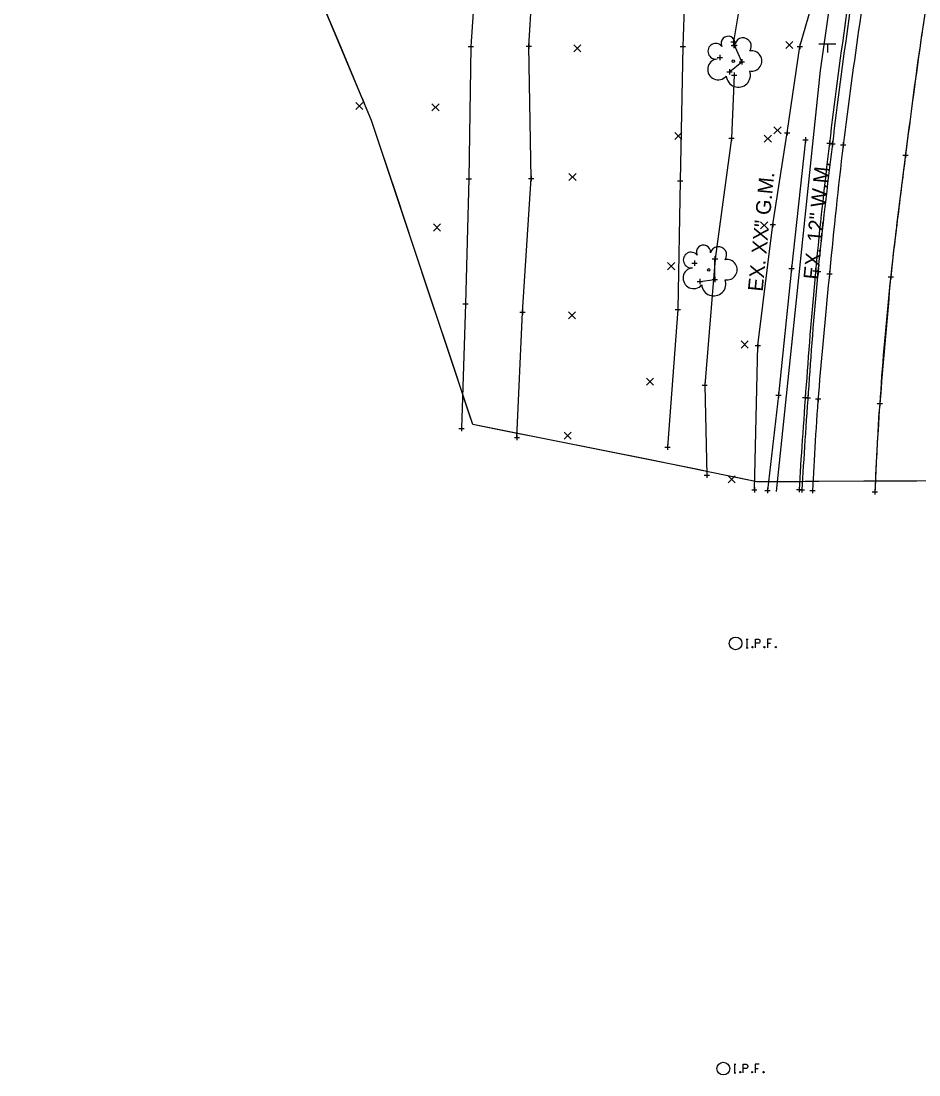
# Model space of a CAD drawing. Extents: x 1324089 to 1329959, y 459099 to 462017.
# Drawn here: x 1324541.1 to 1324710.1, y 459109.6 to 459307.9 of the extents above; entities that cross this region are included whole.
import ezdxf

# ---------------------------------------------------------------- set-up
doc = ezdxf.new("R2010")
doc.units = 0
for name, color, linetype in [('PM_X_Lane_Line', 7, 'Continuous'), ('PM_X_Surveyed_Line', 7, 'Continuous'), ('PV_X_Curb', 7, 'Continuous'), ('PV_X_EOP', 7, 'Continuous'), ('SC_Scratch1', 7, 'Continuous'), ('SN_X_Public', 7, 'Continuous'), ('SV_X_Break_Lines', 7, 'Continuous'), ('SV_X_Mon_Cells_Found', 7, 'Continuous'), ('SV_X_Random_Point', 7, 'Continuous'), ('SV_X_Shot_Marker', 7, 'Continuous'), ('UT_X_Gas', 7, 'Continuous'), ('UT_X_Gas_Text', 7, 'Continuous'), ('UT_X_Water', 7, 'Continuous'), ('UT_X_Water_Text', 7, 'Continuous'), ('VG_X_Cells', 7, 'Continuous'), ('VG_X_Flower_Bed', 7, 'Continuous')]:
    doc.layers.add(name, color=color, linetype=linetype)

msp = doc.modelspace()

# ---------------------------------------------------------------- linework, layer by layer
at = {"layer": 'PM_X_Lane_Line'}
for centre, radius, start, end in [((1325357.86, 459210.87), 654.07, 171.51048, 172.24546), ((1327258.01, 458952.12), 2571.76, 172.24546, 172.61612), ((1326359.8, 459068.52), 1666.03, 172.61612, 173.06999), ((1325632.45, 459156.92), 933.33, 173.06999, 173.6764), ((1339856.26, 457945.01), 15208.41, 175.046029, 175.130785), ((1324762.68, 459253.31), 58.24, 173.6764, 175.046), ((1324869.87, 459221.69), 167.75, 175.1308, 176.845), ((1325603.46, 459181.25), 902.44, 176.84495, 177.58397)]:
    msp.add_arc(centre, radius, start, end, dxfattribs=at)
at = {"layer": 'PM_X_Surveyed_Line'}
msp.add_open_spline([(1324720.83, 459365.01), (1324717.36, 459354.42), (1324715.9, 459334.74), (1324710.69, 459307.46), (1324707.68, 459283.27), (1324704.59, 459259.48), (1324702.8, 459238.34), (1324702.05, 459224.84), (1324701.82, 459219.29)], degree=3, dxfattribs=at)
at = {"layer": 'PV_X_Curb'}
for points in [[(1324554.41, 459525.77), (1324560.16, 459519.51), (1324574.45, 459509.18), (1324595.04, 459493.36), (1324617.9, 459478.11), (1324641.77, 459463.54), (1324665.2, 459452.03), (1324684.98, 459441.52), (1324698.95, 459427.62), (1324704.89, 459409.37), (1324705.69, 459390.23), (1324705.74, 459370.4), (1324703.35, 459350.36), (1324699.71, 459329.94), (1324696.22, 459308.21), (1324693.2, 459284.97), (1324690.54, 459260.98), (1324688.84, 459239.23), (1324687.9, 459225.51), (1324687.54, 459219.73)], [(1324554.61, 459526.26), (1324562.73, 459523.45), (1324573.61, 459508), (1324595.63, 459494.27), (1324618.06, 459478.41), (1324642.02, 459464.01), (1324665.5, 459452.57), (1324685.24, 459441.87), (1324699.44, 459427.92), (1324705.38, 459409.51), (1324706.27, 459390.25), (1324706.24, 459370.35), (1324703.79, 459350.24), (1324700.16, 459329.85), (1324696.79, 459308.11), (1324693.79, 459284.88), (1324690.96, 459260.88), (1324689.32, 459239.14), (1324688.41, 459225.43), (1324688.07, 459219.66)]]:
    msp.add_open_spline(points, degree=3, dxfattribs=at)
at = {"layer": 'PV_X_EOP'}
msp.add_open_spline([(1324556.16, 459527.57), (1324561.48, 459521.01), (1324576.43, 459511.53), (1324596.29, 459495.04), (1324619.32, 459480.24), (1324643.04, 459465.7), (1324666.45, 459454.07), (1324686.66, 459443.46), (1324700.99, 459428.91), (1324707.44, 459410.05), (1324708.19, 459390.35), (1324708.25, 459370.27), (1324705.92, 459350.01), (1324702.09, 459329.59), (1324698.99, 459307.8), (1324695.7, 459284.61), (1324693.29, 459260.58), (1324691.16, 459238.91), (1324690.35, 459225.3), (1324690.06, 459219.55)], degree=3, dxfattribs=at)
at = {"layer": 'SC_Scratch1'}
for p, q in [((1324607.09, 459289.13), (1324595.37, 459317.04)), ((1324626.14, 459231.96), (1324607.09, 459289.13)), ((1324663.15, 459224.6), (1324626.14, 459231.96)), ((1324679.58, 459221.18), (1324663.15, 459224.6)), ((1324759.65, 459221.61), (1324679.58, 459221.18))]:
    msp.add_line(p, q, dxfattribs=at)
msp.add_lwpolyline([(1324719.74, 459221.39), (1324709.74, 459221.34), (1324699.74, 459221.29), (1324690.15, 459221.23), (1324689.74, 459221.23), (1324688.71, 459221.23), (1324688.17, 459221.22), (1324687.77, 459221.22), (1324687.64, 459221.22), (1324683.31, 459221.2), (1324681.76, 459221.19), (1324679.74, 459221.18), (1324679.58, 459221.18), (1324675.12, 459222.1), (1324674.74, 459222.19), (1324670.14, 459223.14), (1324669.95, 459223.18), (1324668.8, 459223.42), (1324663.15, 459224.6), (1324661.31, 459224.97), (1324660.15, 459225.2), (1324650.34, 459227.15), (1324640.54, 459229.1), (1324637.75, 459229.65), (1324634.49, 459230.3), (1324630.73, 459231.05), (1324626.14, 459231.96), (1324625.46, 459234.01), (1324624.46, 459237.01), (1324624.2, 459237.78), (1324622.6, 459242.59), (1324621.3, 459246.5), (1324618.13, 459255.99), (1324614.97, 459265.47), (1324611.81, 459274.96), (1324608.65, 459284.45), (1324607.72, 459287.26), (1324607.09, 459289.13), (1324605.95, 459291.86), (1324605.48, 459292.96), (1324605.13, 459293.8), (1324601.26, 459303.02), (1324597.38, 459312.24)], dxfattribs=at)
at = {"layer": 'SN_X_Public'}
for p, q in [((1324691.3, 459303.58), (1324694.5, 459303.58)), ((1324692.9, 459303.58), (1324692.9, 459301.98)), ((1324692.9, 459303.58), (1324692.9, 459303.58))]:
    msp.add_line(p, q, dxfattribs=at)
at = {"layer": 'SV_X_Break_Lines'}
for p, q in [((1324627.42, 459327.25), (1324625.76, 459303.05)), ((1324636.69, 459303.12), (1324638.1, 459325.97)), ((1324666.42, 459327.01), (1324665.66, 459303.05)), ((1324625.76, 459303.05), (1324625.38, 459278.18)), ((1324637.13, 459278.25), (1324636.69, 459303.12)), ((1324665.66, 459303.05), (1324665.14, 459277.83)), ((1324688.75, 459285.51), (1324686.14, 459261.32)), ((1324625.38, 459278.18), (1324624.77, 459254.65)), ((1324635.49, 459253.09), (1324637.13, 459278.25)), ((1324665.14, 459277.83), (1324664.73, 459253.6)), ((1324686.14, 459261.32), (1324683.65, 459237.51)), ((1324671.69, 459259.25), (1324671.69, 459259.25)), ((1324624.77, 459254.65), (1324623.98, 459231.21)), ((1324634.45, 459229.53), (1324635.49, 459253.09)), ((1324664.73, 459253.6), (1324662.78, 459227.71)), ((1324683.65, 459237.51), (1324681.58, 459219.58))]:
    msp.add_line(p, q, dxfattribs=at)
for points in [[(1324541.09, 459511.12), (1324561.98, 459492.74), (1324584.53, 459475.42), (1324605.25, 459461.38), (1324621.29, 459450.83), (1324632.11, 459444.1), (1324650.07, 459430.27), (1324666.2, 459410.06), (1324661.44, 459407.26), (1324665.74, 459392.42), (1324674.5, 459384.98), (1324677.71, 459376.69), (1324678.67, 459361.24), (1324681.49, 459352.29), (1324680.91, 459341.63), (1324680.37, 459334.21), (1324672.68, 459329.65), (1324675.04, 459320.04), (1324676.26, 459310.34), (1324675.18, 459303.96)], [(1324675.32, 459297.68), (1324674.85, 459285.81), (1324671.78, 459263.15), (1324669.78, 459239.4), (1324670.16, 459222.45)]]:
    msp.add_lwpolyline(points, dxfattribs=at)
at = {"layer": 'SV_X_Mon_Cells_Found'}
for points in [[(1324677.62, 459191.59), (1324677.97, 459191.59)], [(1324677.79, 459189.99), (1324677.79, 459191.59)], [(1324679.36, 459189.99), (1324679.36, 459191.59), (1324679.89, 459191.59), (1324679.94, 459191.58), (1324680.02, 459191.55), (1324680.05, 459191.53), (1324680.09, 459191.5), (1324680.13, 459191.44), (1324680.16, 459191.38), (1324680.18, 459191.28), (1324680.18, 459191.12), (1324680.17, 459191.07), (1324680.15, 459191), (1324680.11, 459190.91), (1324680.06, 459190.87), (1324680.03, 459190.85), (1324679.98, 459190.82), (1324679.89, 459190.81), (1324679.36, 459190.81)], [(1324682.37, 459191.59), (1324681.61, 459191.59), (1324681.61, 459189.99)], [(1324681.61, 459190.81), (1324682.15, 459190.81)], [(1324677.62, 459189.99), (1324677.97, 459189.99)], [(1324678.75, 459190.21), (1324678.81, 459190.21), (1324678.84, 459190.18), (1324678.87, 459190.13), (1324678.87, 459190.07), (1324678.84, 459190.02), (1324678.81, 459189.99), (1324678.75, 459189.99), (1324678.72, 459190.02), (1324678.69, 459190.07), (1324678.69, 459190.13), (1324678.72, 459190.18), (1324678.75, 459190.21)], [(1324681, 459190.21), (1324681.06, 459190.21), (1324681.09, 459190.18), (1324681.12, 459190.13), (1324681.12, 459190.07), (1324681.09, 459190.02), (1324681.06, 459189.99), (1324681, 459189.99), (1324680.97, 459190.02), (1324680.93, 459190.07), (1324680.93, 459190.13), (1324680.97, 459190.18), (1324681, 459190.21)], [(1324683.15, 459190.21), (1324683.2, 459190.21), (1324683.24, 459190.18), (1324683.27, 459190.13), (1324683.27, 459190.07), (1324683.24, 459190.02), (1324683.2, 459189.99), (1324683.15, 459189.99), (1324683.12, 459190.02), (1324683.08, 459190.07), (1324683.08, 459190.13), (1324683.12, 459190.18), (1324683.15, 459190.21)], [(1324675.31, 459111.62), (1324675.66, 459111.62)], [(1324675.48, 459110.02), (1324675.48, 459111.62)], [(1324677.05, 459110.02), (1324677.05, 459111.62), (1324677.58, 459111.62), (1324677.63, 459111.61), (1324677.71, 459111.58), (1324677.74, 459111.56), (1324677.78, 459111.53), (1324677.82, 459111.47), (1324677.85, 459111.41), (1324677.88, 459111.31), (1324677.88, 459111.15), (1324677.86, 459111.1), (1324677.84, 459111.03), (1324677.8, 459110.94), (1324677.75, 459110.9), (1324677.72, 459110.88), (1324677.67, 459110.85), (1324677.58, 459110.84), (1324677.05, 459110.84)], [(1324680.06, 459111.62), (1324679.3, 459111.62), (1324679.3, 459110.02)], [(1324675.31, 459110.02), (1324675.66, 459110.02)], [(1324676.44, 459110.24), (1324676.5, 459110.24), (1324676.53, 459110.21), (1324676.56, 459110.16), (1324676.56, 459110.1), (1324676.53, 459110.05), (1324676.5, 459110.02), (1324676.44, 459110.02), (1324676.41, 459110.05), (1324676.38, 459110.1), (1324676.38, 459110.16), (1324676.41, 459110.21), (1324676.44, 459110.24)], [(1324678.69, 459110.24), (1324678.75, 459110.24), (1324678.78, 459110.21), (1324678.81, 459110.16), (1324678.81, 459110.1), (1324678.78, 459110.05), (1324678.75, 459110.02), (1324678.69, 459110.02), (1324678.66, 459110.05), (1324678.63, 459110.1), (1324678.63, 459110.16), (1324678.66, 459110.21), (1324678.69, 459110.24)], [(1324679.3, 459110.84), (1324679.84, 459110.84)], [(1324680.84, 459110.24), (1324680.9, 459110.24), (1324680.93, 459110.21), (1324680.96, 459110.16), (1324680.96, 459110.1), (1324680.93, 459110.05), (1324680.9, 459110.02), (1324680.84, 459110.02), (1324680.81, 459110.05), (1324680.77, 459110.1), (1324680.77, 459110.16), (1324680.81, 459110.21), (1324680.84, 459110.24)]]:
    msp.add_lwpolyline(points, dxfattribs=at)
for centre in [(1324675.6, 459190.79), (1324673.29, 459110.82)]:
    msp.add_circle(centre, 1.2, dxfattribs=at)
at = {"layer": 'SV_X_Random_Point'}
for p, q in [((1324685.07, 459302.68), (1324686.4, 459304.02)), ((1324685.07, 459304.02), (1324686.4, 459302.68)), ((1324645.16, 459302.08), (1324646.49, 459303.42)), ((1324645.16, 459303.42), (1324646.49, 459302.08)), ((1324604.09, 459291.22), (1324605.42, 459292.55)), ((1324604.09, 459292.55), (1324605.42, 459291.22)), ((1324618.44, 459290.95), (1324619.77, 459292.28)), ((1324618.44, 459292.28), (1324619.77, 459290.95)), ((1324682.83, 459286.63), (1324684.16, 459287.97)), ((1324682.83, 459287.97), (1324684.16, 459286.63)), ((1324664.14, 459285.56), (1324665.47, 459286.9)), ((1324664.14, 459286.9), (1324665.47, 459285.56)), ((1324681, 459285.09), (1324682.34, 459286.43)), ((1324681, 459286.43), (1324682.34, 459285.09)), ((1324644.23, 459277.86), (1324645.57, 459279.19)), ((1324644.23, 459279.19), (1324645.57, 459277.86)), ((1324680.32, 459268.77), (1324681.65, 459270.1)), ((1324680.32, 459270.1), (1324681.65, 459268.77)), ((1324618.72, 459268.37), (1324620.06, 459269.7)), ((1324618.72, 459269.7), (1324620.06, 459268.37)), ((1324662.8, 459261.09), (1324664.14, 459262.43)), ((1324662.8, 459262.43), (1324664.14, 459261.09)), ((1324644.14, 459251.82), (1324645.47, 459253.16)), ((1324644.14, 459253.16), (1324645.47, 459251.82)), ((1324676.64, 459246.36), (1324677.97, 459247.69)), ((1324676.64, 459247.69), (1324677.97, 459246.36)), ((1324658.8, 459239.36), (1324660.13, 459240.69)), ((1324658.8, 459240.69), (1324660.13, 459239.36)), ((1324643.31, 459229.22), (1324644.64, 459230.56)), ((1324643.31, 459230.56), (1324644.64, 459229.22)), ((1324674.22, 459221.01), (1324675.55, 459222.34)), ((1324674.22, 459222.34), (1324675.55, 459221.01))]:
    msp.add_line(p, q, dxfattribs=at)
at = {"layer": 'SV_X_Shot_Marker'}
for p, q in [((1324625.76, 459303.55), (1324625.76, 459302.55)), ((1324636.69, 459303.62), (1324636.69, 459302.62)), ((1324665.66, 459303.55), (1324665.66, 459302.55)), ((1324674.68, 459303.96), (1324675.68, 459303.96)), ((1324675.18, 459304.46), (1324675.18, 459303.46)), ((1324675.18, 459303.96), (1324675.18, 459303.96)), ((1324675.29, 459303.77), (1324675.29, 459302.77)), ((1324675.38, 459303.83), (1324675.38, 459302.83)), ((1324687.69, 459303.61), (1324687.69, 459302.61)), ((1324625.26, 459303.05), (1324626.26, 459303.05)), ((1324625.76, 459303.05), (1324625.76, 459303.05)), ((1324636.19, 459303.12), (1324637.19, 459303.12)), ((1324636.69, 459303.12), (1324636.69, 459303.12)), ((1324665.16, 459303.05), (1324666.16, 459303.05)), ((1324665.66, 459303.05), (1324665.66, 459303.05)), ((1324674.79, 459303.27), (1324675.79, 459303.27)), ((1324674.88, 459303.33), (1324675.88, 459303.33)), ((1324675.29, 459303.27), (1324675.29, 459303.27)), ((1324675.38, 459303.33), (1324675.38, 459303.33)), ((1324687.19, 459303.11), (1324688.19, 459303.11)), ((1324687.69, 459303.11), (1324687.69, 459303.11)), ((1324672.14, 459301), (1324673.14, 459301)), ((1324672.64, 459301.5), (1324672.64, 459300.5)), ((1324672.64, 459301), (1324672.64, 459301)), ((1324676.3, 459300.2), (1324677.3, 459300.2)), ((1324676.3, 459300.2), (1324677.3, 459300.2)), ((1324676.8, 459300.7), (1324676.8, 459299.7)), ((1324676.8, 459300.7), (1324676.8, 459299.7)), ((1324676.8, 459300.2), (1324676.8, 459300.2)), ((1324676.8, 459300.2), (1324676.8, 459300.2)), ((1324673.97, 459298.34), (1324674.97, 459298.34)), ((1324674.47, 459298.84), (1324674.47, 459297.84)), ((1324674.47, 459298.34), (1324674.47, 459298.34)), ((1324674.82, 459297.68), (1324675.82, 459297.68)), ((1324675.32, 459298.18), (1324675.32, 459297.18)), ((1324675.32, 459297.68), (1324675.32, 459297.68)), ((1324674.35, 459285.81), (1324675.35, 459285.81)), ((1324674.85, 459286.31), (1324674.85, 459285.31)), ((1324674.85, 459285.81), (1324674.85, 459285.81)), ((1324684.82, 459286.87), (1324685.82, 459286.87)), ((1324685.32, 459287.37), (1324685.32, 459286.37)), ((1324685.32, 459286.87), (1324685.32, 459286.87)), ((1324688.75, 459286.01), (1324688.75, 459285.01)), ((1324688.25, 459285.51), (1324689.25, 459285.51)), ((1324688.75, 459285.51), (1324688.75, 459285.51)), ((1324692.77, 459284.92), (1324693.77, 459284.92)), ((1324693.27, 459285.42), (1324693.27, 459284.42)), ((1324693.27, 459284.92), (1324693.27, 459284.92)), ((1324693.32, 459284.78), (1324694.32, 459284.78)), ((1324693.82, 459285.28), (1324693.82, 459284.28)), ((1324693.82, 459284.78), (1324693.82, 459284.78)), ((1324695.37, 459284.58), (1324696.37, 459284.58)), ((1324695.87, 459285.08), (1324695.87, 459284.08)), ((1324695.87, 459284.58), (1324695.87, 459284.58)), ((1324707.08, 459282.63), (1324708.08, 459282.63)), ((1324707.58, 459283.13), (1324707.58, 459282.13)), ((1324707.58, 459282.63), (1324707.58, 459282.63)), ((1324624.88, 459278.18), (1324625.88, 459278.18)), ((1324625.38, 459278.68), (1324625.38, 459277.68)), ((1324625.38, 459278.18), (1324625.38, 459278.18)), ((1324636.63, 459278.25), (1324637.63, 459278.25)), ((1324637.13, 459278.75), (1324637.13, 459277.75)), ((1324637.13, 459278.25), (1324637.13, 459278.25)), ((1324664.64, 459277.83), (1324665.64, 459277.83)), ((1324665.14, 459278.33), (1324665.14, 459277.33)), ((1324665.14, 459277.83), (1324665.14, 459277.83)), ((1324682.59, 459270.07), (1324682.59, 459269.07)), ((1324682.09, 459269.57), (1324683.09, 459269.57)), ((1324682.59, 459269.57), (1324682.59, 459269.57)), ((1324667.39, 459262.35), (1324668.39, 459262.35)), ((1324667.89, 459262.85), (1324667.89, 459261.85)), ((1324667.89, 459262.35), (1324667.89, 459262.35)), ((1324671.22, 459263.16), (1324672.22, 459263.16)), ((1324671.28, 459263.15), (1324672.28, 459263.15)), ((1324671.28, 459263.15), (1324672.28, 459263.15)), ((1324671.72, 459263.66), (1324671.72, 459262.66)), ((1324671.72, 459263.16), (1324671.72, 459263.16)), ((1324671.78, 459263.65), (1324671.78, 459262.65)), ((1324671.78, 459263.65), (1324671.78, 459262.65)), ((1324671.78, 459263.15), (1324671.78, 459263.15)), ((1324671.78, 459263.15), (1324671.78, 459263.15)), ((1324685.64, 459261.32), (1324686.64, 459261.32)), ((1324686.14, 459261.82), (1324686.14, 459260.82)), ((1324686.14, 459261.32), (1324686.14, 459261.32)), ((1324690.16, 459260.88), (1324691.16, 459260.88)), ((1324690.62, 459260.77), (1324691.62, 459260.77)), ((1324690.66, 459261.38), (1324690.66, 459260.38)), ((1324690.66, 459260.88), (1324690.66, 459260.88)), ((1324691.12, 459261.27), (1324691.12, 459260.27)), ((1324691.12, 459260.77), (1324691.12, 459260.77)), ((1324692.77, 459260.32), (1324693.77, 459260.32)), ((1324693.27, 459260.82), (1324693.27, 459259.82)), ((1324693.27, 459260.32), (1324693.27, 459260.32)), ((1324704.8, 459260.23), (1324704.8, 459259.23)), ((1324668.35, 459258.87), (1324669.35, 459258.87)), ((1324668.85, 459259.37), (1324668.85, 459258.37)), ((1324668.85, 459258.87), (1324668.85, 459258.87)), ((1324671.19, 459259.25), (1324672.19, 459259.25)), ((1324671.19, 459259.25), (1324672.19, 459259.25)), ((1324671.19, 459259.25), (1324672.19, 459259.25)), ((1324671.69, 459259.75), (1324671.69, 459258.75)), ((1324671.69, 459259.75), (1324671.69, 459258.75)), ((1324671.69, 459259.75), (1324671.69, 459258.75)), ((1324671.69, 459259.25), (1324671.69, 459259.25)), ((1324671.69, 459259.25), (1324671.69, 459259.25)), ((1324671.69, 459259.25), (1324671.69, 459259.25)), ((1324704.3, 459259.73), (1324705.3, 459259.73)), ((1324704.8, 459259.73), (1324704.8, 459259.73)), ((1324624.27, 459254.65), (1324625.27, 459254.65)), ((1324624.77, 459255.15), (1324624.77, 459254.15)), ((1324624.77, 459254.65), (1324624.77, 459254.65)), ((1324664.73, 459254.1), (1324664.73, 459253.1)), ((1324634.99, 459253.09), (1324635.99, 459253.09)), ((1324635.49, 459253.59), (1324635.49, 459252.59)), ((1324635.49, 459253.09), (1324635.49, 459253.09)), ((1324664.23, 459253.6), (1324665.23, 459253.6)), ((1324664.73, 459253.6), (1324664.73, 459253.6)), ((1324679.27, 459246.86), (1324680.27, 459246.86)), ((1324679.77, 459247.36), (1324679.77, 459246.36)), ((1324679.77, 459246.86), (1324679.77, 459246.86)), ((1324669.28, 459239.4), (1324670.28, 459239.4)), ((1324669.78, 459239.9), (1324669.78, 459238.9)), ((1324669.78, 459239.4), (1324669.78, 459239.4)), ((1324683.15, 459237.51), (1324684.15, 459237.51)), ((1324683.65, 459238.01), (1324683.65, 459237.01)), ((1324683.65, 459237.51), (1324683.65, 459237.51)), ((1324688.22, 459237.06), (1324689.22, 459237.06)), ((1324688.7, 459236.97), (1324689.7, 459236.97)), ((1324688.72, 459237.56), (1324688.72, 459236.56)), ((1324688.72, 459237.06), (1324688.72, 459237.06)), ((1324689.2, 459237.47), (1324689.2, 459236.47)), ((1324689.2, 459236.97), (1324689.2, 459236.97)), ((1324690.63, 459236.79), (1324691.63, 459236.79)), ((1324691.13, 459237.29), (1324691.13, 459236.29)), ((1324691.13, 459236.79), (1324691.13, 459236.79)), ((1324702.73, 459236.42), (1324702.73, 459235.42)), ((1324702.23, 459235.92), (1324703.23, 459235.92)), ((1324702.73, 459235.92), (1324702.73, 459235.92)), ((1324623.48, 459231.21), (1324624.48, 459231.21)), ((1324623.98, 459231.71), (1324623.98, 459230.71)), ((1324623.98, 459231.21), (1324623.98, 459231.21)), ((1324633.95, 459229.53), (1324634.95, 459229.53)), ((1324634.45, 459230.03), (1324634.45, 459229.03)), ((1324634.45, 459229.53), (1324634.45, 459229.53)), ((1324662.78, 459228.21), (1324662.78, 459227.21)), ((1324662.28, 459227.71), (1324663.28, 459227.71)), ((1324662.78, 459227.71), (1324662.78, 459227.71)), ((1324669.66, 459222.45), (1324670.66, 459222.45)), ((1324670.16, 459222.95), (1324670.16, 459221.95)), ((1324670.16, 459222.45), (1324670.16, 459222.45)), ((1324678.63, 459219.68), (1324679.63, 459219.68)), ((1324679.13, 459220.18), (1324679.13, 459219.18)), ((1324679.13, 459219.68), (1324679.13, 459219.68)), ((1324681.08, 459219.58), (1324682.08, 459219.58)), ((1324681.58, 459220.08), (1324681.58, 459219.08)), ((1324681.58, 459219.58), (1324681.58, 459219.58)), ((1324687.04, 459219.73), (1324688.04, 459219.73)), ((1324687.54, 459220.23), (1324687.54, 459219.23)), ((1324687.54, 459219.73), (1324687.54, 459219.73)), ((1324687.57, 459219.66), (1324688.57, 459219.66)), ((1324688.07, 459220.16), (1324688.07, 459219.16)), ((1324688.07, 459219.66), (1324688.07, 459219.66)), ((1324689.56, 459219.55), (1324690.56, 459219.55)), ((1324690.06, 459220.05), (1324690.06, 459219.05)), ((1324690.06, 459219.55), (1324690.06, 459219.55)), ((1324701.32, 459219.29), (1324702.32, 459219.29)), ((1324701.82, 459219.79), (1324701.82, 459218.79)), ((1324701.82, 459219.29), (1324701.82, 459219.29))]:
    msp.add_line(p, q, dxfattribs=at)
at = {"layer": 'UT_X_Gas'}
msp.add_lwpolyline([(1324679.13, 459219.68), (1324679.77, 459246.86), (1324682.59, 459269.57), (1324685.32, 459286.87), (1324687.69, 459303.11), (1324691.63, 459316.77), (1324694.22, 459329.35), (1324695.55, 459341.62), (1324697.28, 459354.27), (1324699.79, 459367.29)], dxfattribs=at)
at = {"layer": 'UT_X_Water'}
msp.add_lwpolyline([(1324683.28, 459219.36), (1324691.61, 459298.59), (1324698.63, 459347.92), (1324699.63, 459354.94), (1324721.27, 459442.34), (1324756.06, 459540.19), (1324772.19, 459580.09), (1324802.34, 459646.28), (1324825.1, 459690.99), (1324841.26, 459722.73), (1324902.17, 459810.08), (1324917.22, 459828.86)], dxfattribs=at)
at = {"layer": 'VG_X_Cells'}
for centre in [(1324675.17, 459300.32), (1324670.54, 459261.05)]:
    msp.add_circle(centre, 0.24, dxfattribs=at)
for centre, radius, start, end in [((1324671.86, 459302.18), 1.47, 39.0625, 279.5412), ((1324674.19, 459303.69), 1.32, 354.0047, 205.9741), ((1324677, 459303.15), 1.55, 323.83, 165.0376), ((1324678.63, 459300.35), 1.91, 259.1453, 101.4596), ((1324672.32, 459298.77), 1.97, 96.1722, 320.5737), ((1324676.12, 459297.71), 2.28, 184.9476, 19.4572), ((1324667.23, 459262.91), 1.47, 39.0625, 279.5412), ((1324669.56, 459264.42), 1.32, 354.0047, 205.9741), ((1324672.37, 459263.88), 1.55, 323.83, 165.0376), ((1324674, 459261.09), 1.91, 259.1453, 101.4596), ((1324667.69, 459259.5), 1.97, 96.1722, 320.5737), ((1324671.49, 459258.44), 2.28, 184.9476, 19.4572)]:
    msp.add_arc(centre, radius, start, end, dxfattribs=at)
at = {"layer": 'VG_X_Flower_Bed'}
for p, q in [((1324675.38, 459303.33), (1324675.29, 459303.27)), ((1324676.8, 459300.2), (1324675.38, 459303.33)), ((1324674.47, 459298.34), (1324676.8, 459300.2)), ((1324671.69, 459259.25), (1324671.72, 459263.16)), ((1324671.72, 459263.16), (1324671.72, 459263.16)), ((1324668.85, 459258.87), (1324671.69, 459259.25))]:
    msp.add_line(p, q, dxfattribs=at)
msp.add_lwpolyline([(1324671.78, 459263.15), (1324671.72, 459263.16)], dxfattribs=at)

# ---------------------------------------------------------------- texts
at = {"layer": 'UT_X_Gas_Text'}
msp.add_text('EX. XX" G.M.', height=2.8, rotation=84.333, dxfattribs=at).set_placement((1324680.69, 459256.91))
at = {"layer": 'UT_X_Water_Text'}
msp.add_text('EX. 12" W.M.', height=2.8, rotation=84.333, dxfattribs=at).set_placement((1324691.14, 459259.15))

doc.saveas('drawing.dxf')
